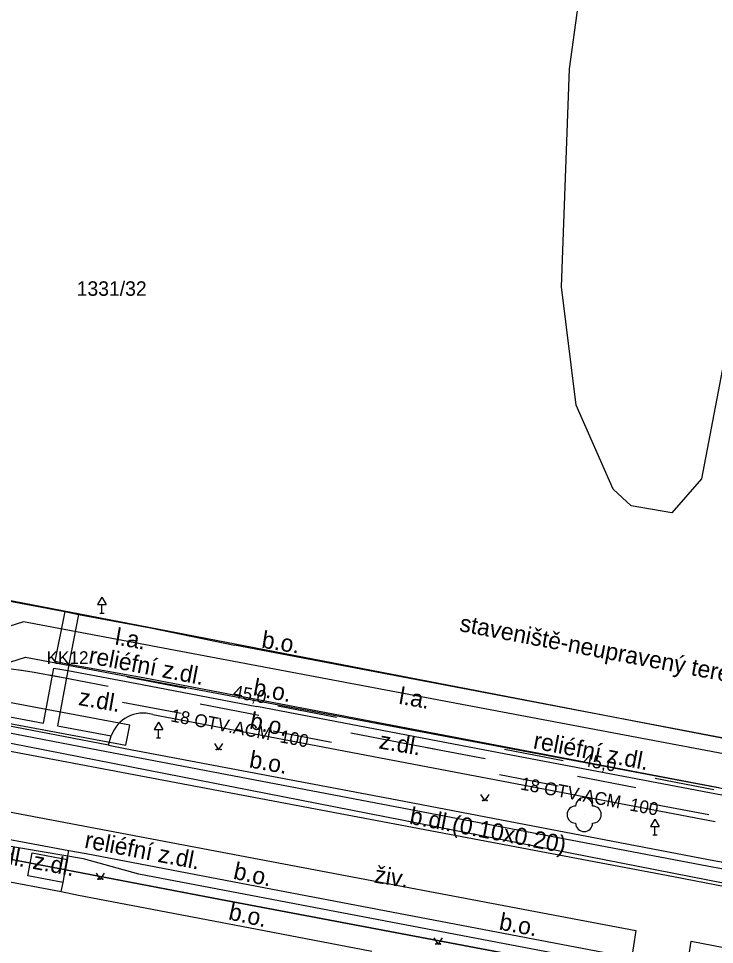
# Model space of a CAD drawing. Extents: x -601602 to -600882, y -1162594 to -1161950.
# Drawn here: x -601275.4 to -601234.6, y -1162334.3 to -1162279.9 of the extents above; entities that cross this region are included whole.
import ezdxf

# ---------------------------------------------------------------- set-up
doc = ezdxf.new("R2010")
doc.units = 0
for name, color, linetype in [('KN_Hranice parcel', 7, 'Continuous'), ('KN_Parcelní čísla', 7, 'Continuous'), ('KN_Věcná břemena k části', 7, 'Continuous'), ('VRSTVA 1', 7, 'Continuous'), ('Vrstva 13', 7, 'Continuous'), ('Vrstva 14', 7, 'Continuous'), ('Vrstva 16', 7, 'Continuous'), ('VRSTVA 3', 7, 'Continuous'), ('Vrstva 6', 7, 'Continuous'), ('Vrstva 8', 7, 'Continuous')]:
    doc.layers.add(name, color=color, linetype=linetype)

msp = doc.modelspace()

# ---------------------------------------------------------------- linework, layer by layer
at = {"layer": 'KN_Hranice parcel'}
for points in [[(-601145.61, -1162287.55), (-601173.25, -1162282.27), (-601173.4, -1162283.06), (-601172.3, -1162283.24), (-601179.38, -1162320.27), (-601217.44, -1162312.99), (-601210.35, -1162275.97), (-601209.33, -1162276.17), (-601209.18, -1162275.41), (-601228.61, -1162271.66), (-601235.35, -1162306.96), (-601237.09, -1162308.94), (-601239.47, -1162308.54), (-601240.53, -1162307.56), (-601242.69, -1162302.63), (-601243.55, -1162295.69), (-601243.08, -1162282.88), (-601242.03, -1162275.2), (-601241.16, -1162270.7), (-601240.67, -1162268.72)], [(-601294.47, -1162297.06), (-601294, -1162297.81), (-601291.4, -1162299.81), (-601288.77, -1162302.11), (-601286.44, -1162304.9), (-601284.62, -1162307.84), (-601283.14, -1162310.6), (-601281.69, -1162312.15), (-601279.73, -1162313.35), (-601233.13, -1162322.35), (-601185.37, -1162331.34)], [(-600919.037, -1162396.971), (-600927.7, -1162395.33), (-600949.5, -1162391.18), (-600985.92, -1162384.31), (-601061.31, -1162370.08), (-601128.39, -1162357.28), (-601192.59, -1162345.07), (-601263.97, -1162331.56), (-601288.82, -1162326.8), (-601298.71, -1162324.89), (-601298.28, -1162322.82), (-601301.35, -1162321.33), (-601304.05, -1162318.46), (-601304.21, -1162314.16), (-601302.32, -1162304.33), (-601302.09, -1162303.45)], [(-601296.68, -1162304.46), (-601298.54, -1162310.66), (-601297.99, -1162318.35), (-601285.76, -1162320.53), (-601213.14, -1162334.77)]]:
    msp.add_lwpolyline(points, dxfattribs=at)
at = {"layer": 'KN_Věcná břemena k části'}
for points in [[(-601209.38, -1162327.74), (-601275.12, -1162315.35), (-601278.09, -1162316.28), (-601278.9, -1162317.85), (-601279.27, -1162317.66), (-601286.61, -1162307.54), (-601294.51, -1162297.19), (-601295.28, -1162296.17), (-601298.52, -1162290.66), (-601299.33, -1162292.84), (-601299.4, -1162293.1), (-601296.94, -1162297.29), (-601295.21, -1162299.55), (-601288.21, -1162308.74), (-601280.59, -1162319.26), (-601279.52, -1162319.76), (-601279.87, -1162321.69), (-601281.06, -1162328.29), (-601279.1, -1162328.66), (-601277.9, -1162322.07), (-601277.4, -1162319.32), (-601276.69, -1162317.94), (-601275, -1162317.41), (-601209.74, -1162329.7)], [(-601128.25, -1162351.23), (-601195.49, -1162338.35), (-601236.98, -1162330.32), (-601280.77, -1162322.03), (-601281.32, -1162321.4), (-601285.76, -1162320.53), (-601290.19, -1162319.74), (-601285.4, -1162325.24), (-601285.76, -1162327.39), (-601282.42, -1162328.03), (-601281.97, -1162325.36), (-601239.19, -1162333.47), (-601239.6, -1162336.17), (-601236.36, -1162336.79), (-601235.95, -1162334.09), (-601196.15, -1162341.79), (-601130.52, -1162354.26)], [(-601277.19, -1162321.08), (-601269.11, -1162322.59), (-601268.89, -1162321.41), (-601276.91, -1162319.91)], [(-600974.13, -1162386.23), (-601268.36, -1162330.16), (-601271.59, -1162329.26), (-601278.66, -1162328.07)], [(-601279.98, -1162328.49), (-601263.97, -1162331.56), (-601192.59, -1162345.07)]]:
    msp.add_lwpolyline(points, dxfattribs=at)
at = {"layer": 'VRSTVA 1'}
msp.add_lwpolyline([(-601275.371, -1162318.188), (-601275.39, -1162318.185), (-601276.28, -1162318.06), (-601281.81, -1162316.83), (-601284.51, -1162316.21), (-601287.04, -1162314.12), (-601288.27, -1162312.16), (-601291.39, -1162307.21), (-601292.79, -1162304.98), (-601295.01, -1162302.44), (-601297.08, -1162300.063)], dxfattribs=at)
at = {"layer": 'Vrstva 13'}
for p, q in [((-601278.92, -1162313.57), (-601272.7, -1162314.74)), ((-601272.7, -1162314.74), (-601273.29, -1162317.66)), ((-601272.7, -1162314.74), (-601271.9, -1162314.91)), ((-601271.9, -1162314.91), (-601272.46, -1162317.82)), ((-601271.9, -1162314.91), (-601267.67, -1162315.7)), ((-601267.67, -1162315.7), (-601262.74, -1162316.72)), ((-601246.99, -1162319.71), (-601262.74, -1162316.72)), ((-601273.29, -1162317.66), (-601272.46, -1162317.82)), ((-601273.95, -1162321.29), (-601273.34, -1162318.06)), ((-601273.34, -1162318.06), (-601272.52, -1162318.21)), ((-601272.52, -1162318.21), (-601273.13, -1162321.44)), ((-601272.46, -1162317.82), (-601272.52, -1162318.21)), ((-601272.52, -1162318.21), (-601268.15, -1162319.03)), ((-601272.46, -1162317.82), (-601268.1, -1162318.62)), ((-601268.1, -1162318.62), (-601261.36, -1162319.91)), ((-601268.15, -1162319.03), (-601261.43, -1162320.31)), ((-601261.36, -1162319.91), (-601234.33, -1162325.07)), ((-601230.93, -1162322.77), (-601246.99, -1162319.71)), ((-601247.65, -1162322.96), (-601261.43, -1162320.31)), ((-601277.06, -1162320.7), (-601273.95, -1162321.29)), ((-601267.54, -1162320.78), (-601234.54, -1162327.06)), ((-601270.13, -1162322.58), (-601277.16, -1162321.24)), ((-601273.13, -1162321.44), (-601269.97, -1162322.04)), ((-601277.08, -1162321.65), (-601270.76, -1162322.85)), ((-601270.13, -1162322.58), (-601269.97, -1162322.04)), ((-601270.13, -1162322.58), (-601269.15, -1162322.77)), ((-601270.76, -1162322.85), (-601253.22, -1162326.2)), ((-601269.15, -1162322.77), (-601253.19, -1162325.8)), ((-601231.56, -1162326.02), (-601247.65, -1162322.96)), ((-601253.19, -1162325.8), (-601234.94, -1162329.29)), ((-601253.22, -1162326.2), (-601235.01, -1162329.67)), ((-601277.34, -1162327.85), (-601272.45, -1162328.77)), ((-601274.87, -1162330.25), (-601274.62, -1162328.91)), ((-601274.62, -1162328.91), (-601272.55, -1162329.3)), ((-601272.55, -1162329.3), (-601272.45, -1162328.77)), ((-601272.45, -1162328.77), (-601271.45, -1162328.94)), ((-601271.45, -1162328.94), (-601261.44, -1162330.85)), ((-601272.8, -1162330.64), (-601272.55, -1162329.3)), ((-601235.01, -1162329.67), (-601217.57, -1162332.99)), ((-601234.94, -1162329.29), (-601217.1, -1162332.68)), ((-601277.79, -1162330.26), (-601272.91, -1162331.18)), ((-601272.8, -1162330.64), (-601274.87, -1162330.25)), ((-601272.91, -1162331.18), (-601272.8, -1162330.64)), ((-601261.44, -1162330.85), (-601254.35, -1162332.21)), ((-601272.91, -1162331.18), (-601271.9, -1162331.39)), ((-601271.9, -1162331.39), (-601261.91, -1162333.29)), ((-601254.35, -1162332.21), (-601236.05, -1162335.69)), ((-601261.91, -1162333.29), (-601254.69, -1162334.68))]:
    msp.add_line(p, q, dxfattribs=at)
msp.add_arc((-601268.093, -1162322.687), 1.985, 73.823, 160.9922, dxfattribs=at)
at = {"layer": 'Vrstva 14'}
msp.add_circle((-601242.23, -1162326.66), 0.0005, dxfattribs=at)
for centre, start, end in [((-601242.23, -1162326.16), 0, 180), ((-601242.73, -1162326.66), 90, 270), ((-601241.73, -1162326.66), 270, 90), ((-601242.23, -1162327.16), 180, 360)]:
    msp.add_arc(centre, 0.5, start, end, dxfattribs=at)
at = {"layer": 'VRSTVA 3'}
for points in [[(-601263.921, -1162322.485), (-601263.671, -1162322.86), (-601263.421, -1162322.485)], [(-601248.305, -1162325.482), (-601248.055, -1162325.857), (-601247.805, -1162325.482)], [(-601270.865, -1162330.091), (-601270.615, -1162330.466), (-601270.365, -1162330.091)], [(-601251.046, -1162333.898), (-601250.796, -1162334.273), (-601250.546, -1162333.898)]]:
    msp.add_lwpolyline(points, dxfattribs=at)
for centre in [(-601263.796, -1162322.835), (-601263.546, -1162322.835), (-601248.18, -1162325.832), (-601247.93, -1162325.832), (-601270.74, -1162330.441), (-601270.49, -1162330.441), (-601250.921, -1162334.248), (-601250.671, -1162334.248)]:
    msp.add_circle(centre, 0.025, dxfattribs=at)
at = {"layer": 'Vrstva 8'}
for p, q in [((-601270.52, -1162313.897), (-601270.77, -1162314.33)), ((-601270.52, -1162313.897), (-601270.27, -1162314.33)), ((-601270.77, -1162314.33), (-601270.27, -1162314.33)), ((-601270.52, -1162314.83), (-601270.52, -1162314.33)), ((-601270.645, -1162314.83), (-601270.395, -1162314.83)), ((-601274.847, -1162318.261), (-601275.371, -1162318.188)), ((-601274.5, -1162318.31), (-601275.371, -1162318.188)), ((-601273.027, -1162318.593), (-601274.5, -1162318.31)), ((-601270.157, -1162319.144), (-601273.594, -1162318.484)), ((-601265.596, -1162319.257), (-601269.033, -1162318.596)), ((-601265.879, -1162320.73), (-601269.316, -1162320.07)), ((-601261.318, -1162320.842), (-601264.756, -1162320.182)), ((-601256.758, -1162320.955), (-601260.195, -1162320.294)), ((-601267.2, -1162321.227), (-601267.45, -1162321.66)), ((-601267.2, -1162321.227), (-601266.95, -1162321.66)), ((-601267.45, -1162321.66), (-601266.95, -1162321.66)), ((-601267.2, -1162322.16), (-601267.2, -1162321.66)), ((-601257.041, -1162322.428), (-601260.478, -1162321.767)), ((-601252.48, -1162322.54), (-601255.917, -1162321.88)), ((-601267.325, -1162322.16), (-601267.075, -1162322.16)), ((-601251.007, -1162322.823), (-601252.48, -1162322.54)), ((-601248.027, -1162323.395), (-601251.464, -1162322.735)), ((-601243.466, -1162323.507), (-601246.903, -1162322.847)), ((-601243.749, -1162324.98), (-601247.186, -1162324.32)), ((-601239.188, -1162325.093), (-601242.626, -1162324.432)), ((-601234.628, -1162325.205), (-601238.065, -1162324.545)), ((-601234.911, -1162326.678), (-601238.348, -1162326.018)), ((-601238.08, -1162326.917), (-601238.33, -1162327.35)), ((-601238.08, -1162326.917), (-601237.83, -1162327.35)), ((-601238.33, -1162327.35), (-601237.83, -1162327.35)), ((-601238.08, -1162327.85), (-601238.08, -1162327.35)), ((-601238.205, -1162327.85), (-601237.955, -1162327.85))]:
    msp.add_line(p, q, dxfattribs=at)

# ---------------------------------------------------------------- texts
at = {"layer": 'KN_Parcelní čísla'}
msp.add_text('1331/32', height=0.85, dxfattribs=at).set_placement((-601272, -1162296.21))
at = {"layer": 'Vrstva 16'}
for s, rotation, p in [('staveniště-neupravený terén', 349.2314, (-601249.591, -1162315.883)), ('l.a.', 350.002, (-601269.795, -1162316.67)), ('b.o.', 350.7722, (-601261.194, -1162316.853)), ('reliéfní z.dl.', 349.1077, (-601271.345, -1162317.768)), ('b.o.', 349.1539, (-601261.697, -1162319.644)), ('l.a.', 350.002, (-601253.145, -1162320.149)), ('z.dl.', 350.0342, (-601271.938, -1162320.222)), ('b.o.', 347.8081, (-601261.906, -1162321.599)), ('z.dl.', 350.0342, (-601254.309, -1162322.77)), ('reliéfní z.dl.', 349.1077, (-601245.262, -1162322.765)), ('b.o.', 349.7224, (-601261.923, -1162323.88)), ('b.dl.(0.10x0.20)', 349.2109, (-601252.52, -1162327.189)), ('reliéfní z.dl.', 349.1077, (-601271.585, -1162328.596)), ('z.dl.', 349.345, (-601277.474, -1162329.295)), ('z.dl.', 349.345, (-601274.626, -1162329.829)), ('b.o.', 347.8081, (-601262.857, -1162330.412)), ('živ.', 350.833, (-601254.586, -1162330.644)), ('b.o.', 347.8081, (-601263.141, -1162332.802)), ('b.o.', 349.2371, (-601247.265, -1162333.395))]:
    msp.add_text(s, height=1, rotation=rotation, dxfattribs=at).set_placement(p)
at = {"layer": 'Vrstva 6'}
msp.add_text('KK12', height=0.75, dxfattribs=at).set_placement((-601273.76, -1162317.82))
for s, p in [('45,0', (-601262.866, -1162319.781)), ('18 OTV.ACM  100', (-601266.524, -1162321.18)), ('45,0', (-601242.347, -1162323.781)), ('18 OTV.ACM  100', (-601246.005, -1162325.18))]:
    msp.add_text(s, height=0.75, rotation=349.1275, dxfattribs=at).set_placement(p)

doc.saveas('drawing.dxf')
